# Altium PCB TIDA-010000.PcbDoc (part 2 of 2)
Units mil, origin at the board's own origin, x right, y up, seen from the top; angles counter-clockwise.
Board outline 6158.37 x 2561.06 mil, 2 copper layers (Top Layer, Bottom Layer), stack 62 mil thick; 145 components, 51 nets, 285 pads, 57 vias.
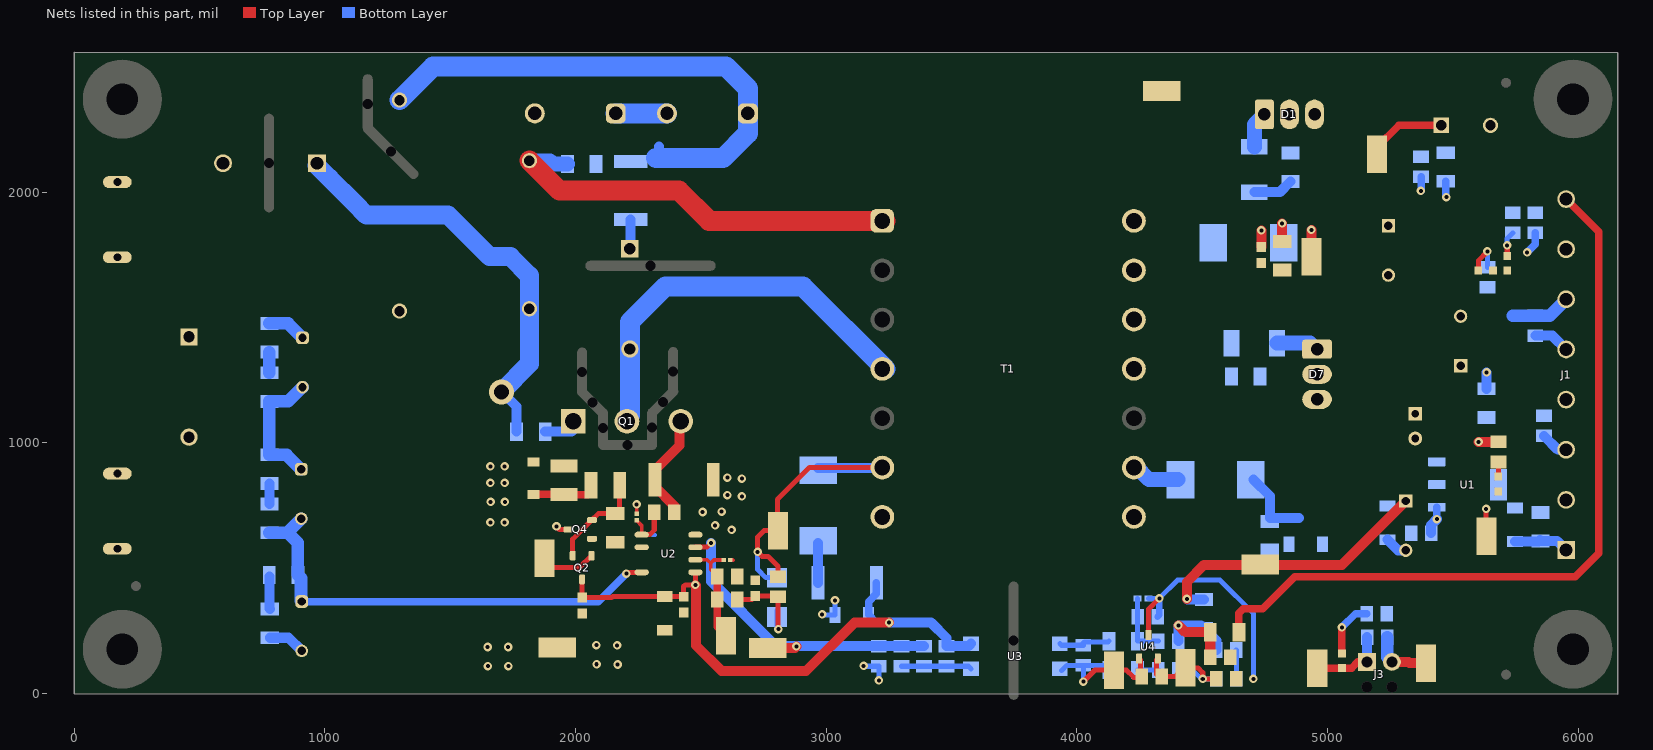
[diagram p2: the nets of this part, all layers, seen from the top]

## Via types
v1: diameter 34, hole 16, Top Layer to Bottom Layer, tented both sides, 56 vias
v2: diameter 100, hole 60, Top Layer to Bottom Layer, tented both sides, 1 vias

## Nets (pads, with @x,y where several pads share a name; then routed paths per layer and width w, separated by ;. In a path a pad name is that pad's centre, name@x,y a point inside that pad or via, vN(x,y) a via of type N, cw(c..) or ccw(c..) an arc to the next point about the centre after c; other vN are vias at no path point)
3V3DC: C26.1 J1.2 R52.2 TP7.1 U1.2 U1.4 | length 110.6
  Top Layer w20: v1(5633.37,737) 5633.37,628.35 TP7.1@5634.72,627
5V_ISO: C18.1 C21.1 C23.1 D13.1 J3.2 R17.2 R43.2 TP4.1 | length 542.6
  Top Layer w40: J3.2@5257.31,126.5 5322.37,126.5 5326.87,122 TP4.1@5393.37,122
  Bottom Layer w40: D13.1@4704.22,854 4770.22,788 4770.22,700.09 4887.13,700.09
  Bottom Layer w50: C23.1@5237.88,225 5237.88,145.93 J3.2@5257.31,126.5
5VDC: C13.1 C16.1 C17.1 C25.1 J1.4 L1.2 R11.2 R35.2 R54.2 TP3.1 U1.3 | length 1218.9
  Top Layer w40: v1(4439.37,378) 4439.37,445.56 4507.81,514 4643.83,514 5057.8,514 C16.1@5312.22,768.43 ; v1(5603.22,1004) R35.2@5682.88,1004
  Bottom Layer w40: v1@4442.28,375.09 R54.2@4507.37,375.09
15VDC: C4.1 C8.1 C12.1 D6.1 J1.6 R5.2 R45.2 TP2.1 | length 485
  Top Layer w40: C8.1@4736.22,1781.5 v1(4736.22,1848) ; R5.2@4819.22,1804.09 v1(4819.22,1875.71) ; TP2.1@4936.22,1743 v1(4936.22,1850)
  Bottom Layer w50: 5739.16,1508 C12.1@5829.16,1508 5887.16,1508 J1.6@5952.16,1573
24VDC: C1.1 C3.1 C5.1 C11.1 D1.2 J1.8 R2.2 R44.2 R53.2 TP1.1 | length 3397.5
  Top Layer w30: R53.2@4646.46,245 4646.37,245.09 4646.37,320.37 4664.47,338.47 4741.69,338.47 4869.22,466 5987.88,466 6081.88,560 6081.88,1843.28 J1.8@5952.16,1973 ; TP1.1@5197.22,2151 5197.22,2178.85 5285.37,2267 C3.1@5453.4,2267
CS: C22.1 R21.2 U2.5 | length 194.6
  Top Layer w15: C22.1@2244.22,690.96 2263.94,671.24 U2.5@2263.94,634
  Top Layer w20: U2.5@2263.94,634 2295.91,634 2314.22,652.31 R21.2@2314.22,723.9
FB: C34.2 R36.1 R39.2 TP13.1 U2.3 | length 1295.5
  Top Layer w20: U2.3@2478.5,584 2524.22,584 v1(2541.22,601)
  Top Layer w40: TP13.1@2767.22,182 2874.72,182 v1(2881.22,188.5)
  Bottom Layer w40: v1(2541.22,601) 2541.22,448 2800.04,189.18 R39.2@3210.09,189.18 C34.2@3390.09,189.18
Gate: D24.2 Q1.1 R19.2 R50.2 | length 115.2
  Bottom Layer w40: R50.2@1879.31,1045 1983.22,1045 Q1.1@1991.22,1053
GND: C3.2 C4.2 C5.2 C8.2 C11.2 C12.2 C13.2 C15.2 C16.2 C17.2 C25.2 C26.2 C27.1 C44.2 D18.2 D20.2 D26.2 D27.2 J1.1 J1.3 J1.5 J1.7 R2.1 R5.1 R11.1 R24.1 R52.1 T1.11 TP11.1 U1.1 U4.3 | length 1959.2
  Top Layer w20: U4.3@4285.7,234.24 4285.7,336.77 v1(4328.93,380)
  Bottom Layer w20: D18.2@4285.93,380 v1(4328.93,380) 4401.8,452.87 4571.35,452.87 4704.04,320.18 v1(4704.04,59.18)
  Bottom Layer w25: C27.1@4322.28,307 4328.93,313.65 v1(4328.93,380)
  Bottom Layer w30: v1(5372.22,2006) 5373.31,2007.09 C5.2@5373.31,2062 ; v1(5436.19,696) U1.1@5436.19,743.45 ; R2.1@5472.31,2043.91 5472.31,1982.91 v1(5474.22,1981) ; v1(5796.88,1760) 5829.16,1792.27 C11.2@5829.16,1838
  Bottom Layer w40: C25.2@5239.22,614.07 5281.72,571.57 C16.2@5312.22,571.57 ; C17.2@5413.31,640 5413.31,673.12 v1(5436.19,696) ; R11.1@5634.88,1216.09 v1(5634.88,1281.66) ; C26.2@5747.88,607.07 5842.04,607.07 R52.1@5847.05,612.08 ; C12.2@5829.16,1428 5897.16,1428 J1.5@5952.16,1373 ; R52.1@5850.22,608.91 5916.24,608.91 J1.1@5952.16,573 ; C13.2@5863.88,1028 5918.88,973 J1.3@5952.16,973
HV_START: C14.2 C20.1 R12.1 R15.2 U2.8 | length 1853.8
  Top Layer w20: v1(2203.22,479) 2208.22,484 U2.8@2263.94,484
  Bottom Layer w30: C20.1@905,370.33 C20.1@907.91,367.43 2091.65,367.43 v1(2203.22,479)
  Bottom Layer w50: R12.1@778.91,642.04 779.5,642.63 851.77,642.63 ; C20.1@905,370.33 905,461.18 R15.2@892.68,473.5 892.68,601.72 851.77,642.63 ; C14.2@905.91,698.1 905.91,696.77 851.77,642.63
ISO_GND: C18.2 C21.2 C23.2 D25.2 J3.1 R17.1 T1.8 TP10.1 | length 307.9
  Top Layer w30: TP10.1@4959.22,102 5056.84,102 D25.2@5057.37,101.47 5095.84,101.47 5120.87,126.5 J3.1@5157.31,126.5
  Top Layer w40: J3.1@5156.98,126.83 J3.1@5157.31,126.5
  Bottom Layer w40: J3.1@5157.31,126.5 5157.31,224.42 C23.2@5157.88,225
NetC1_2: C1.2 R1.2 | length 161.8
  Bottom Layer w40: R1.2@4708.22,2000.45 4809.98,2000.45 C1.2@4852.44,2042.91
NetC2_2: C2.2 D5.1 R4.1 R6.2 | length 2067
  Bottom Layer w40: 2333.08,2183.14 2333.22,2183
  Bottom Layer w80: R4.1@1298.11,2367.87 1431.3,2501.06 2601.16,2501.06 2687.69,2414.53 D5.1@2687.69,2314.78 2687.69,2235.47 2589.22,2137 2321.34,2137
NetC9_2: C9.2 C14.1 R8.1 R10.2 | length 519.3
  Bottom Layer w50: C14.1@905.91,894.95 848,952.86 R10.2@778.91,952.86 R8.1@778.91,1165.6 853.93,1165.6 C9.2@910.91,1222.57
NetC10_1: C10.1 C15.1 D7.2 L1.1
NetC10_2: C10.2 R7.2
NetC27_2: C27.2 D18.1 R9.1 R28.2 | length 254.3
  Bottom Layer w20: D18.1@4242.62,380 4242.28,379.65 C27.2@4242.28,307 4242.18,306.9 R28.2@4242.18,209.18 4325.19,209.18 R9.1@4325.37,209
NetC28_1: C28.1 R29.1 R37.2 TP14.1 U2.2 | length 441.3
  Top Layer w15: U2.2@2478.5,534 2525.05,534 2539.23,519.82 ; R37.2@2566.22,467 2539.23,493.99 2539.23,519.82 ; C28.1@2592.23,532.81 2552.22,532.81 2539.23,519.82
  Top Layer w20: R37.2@2571.22,449 R37.2@2572.22,450
  Top Layer w30: R37.2@2566.22,467 2566.22,377 R29.1@2565.22,376 2565.22,266 TP14.1@2600.22,231
NetC31_2: C31.2 C34.1 R36.2 U3.3 | length 282
  Bottom Layer w20: R36.2@3300.09,109.18 C34.1@3390.09,109.19 C31.2@3480.09,109.18 3567.93,109.18 U3.3@3577.93,99.18
NetC32_1: C32.1 C35.2 R24.2 R31.1 TP9.1 U4.2 | length 490
  Top Layer w20: C35.2@4317.2,77 4317.2,133.85 U4.2@4323.1,139.76 ; C35.2@4338.69,68 4392.22,68 4427.22,103 4483.22,103 4502.4,83.82 v1(4502.4,59.18) R24.2@4556.7,59.18
  Bottom Layer w20: C32.1@4405.09,94.18 4461.04,94.18 v1@4496.04,59.18 ; v1(4502.4,59.18) R31.1@4556.7,59.18
NetC32_2: C32.2 R32.1 | length 82.9
  Bottom Layer w20: R32.1@4242.18,94.18 C32.2@4325.09,94.18
NetC33_1: C33.1 D8.2 R27.1 R29.2 | length 376
  Top Layer w20: R29.2@2645.22,376 2703.41,376 C33.1@2716.91,389.5 2804.72,389.5 R27.1@2808.22,386 2808.22,258.41 v1(2809.22,257.41)
  Bottom Layer w20: D8.2@2804.22,332.26 2804.22,262.41 v1(2809.22,257.41)
NetC35_1: C35.1 R13.1 R32.2 TP5.1 U3.2 U4.1 | length 615.1
  Top Layer w20: v1(4026.37,48) 4072.37,94 TP5.1@4149.22,94 4197.8,94 4226.8,65 C35.1@4254.2,65 ; U4.1@4248.3,139.76 4254.2,133.85 C35.1@4254.2,65 ; C35.1@4258.69,68 4255.69,65 C35.1@4254.2,65
  Bottom Layer w20: U3.2@3939.34,92.1 3960.24,113 R13.1@4025.9,113 ; v1(4026.37,48) 4025.9,48.47 R13.1@4025.9,113 ; R32.2@4125.92,92.1 R32.2@4128,94.18 4109.19,113 R13.1@4025.9,113
NetC44_1: C44.1 R9.2 R26.2 R53.1 R54.1 | length 517.4
  Top Layer w40: v1(4405.37,272.66) 4433.03,245 R53.1@4532.28,245 ; C44.1@4526.74,147.09 C44.1@4528.83,145 ; C44.1@4532.37,145 R53.1@4532.37,242.91
  Bottom Layer w40: R9.2@4405.37,209 v1(4405.37,272.66) 4495.62,272.66 R54.1@4507.37,260.91 4556.7,211.59 R26.2@4556.7,174.18 R26.2@4556.37,174.51
NetD1_1: D1.1 D1.3 R1.1 T1.14 | length 146
  Bottom Layer w60: R1.1@4708.22,2181.55 4708.22,2270.73 D1.1@4748.37,2310.88
NetD2_1: D2.1 D5.2 | length 204.2
  Bottom Layer w80: D2.1@2160.64,2314.78 D5.2@2364.86,2314.78
NetD3_2: D3.2 F2.1 F2.2
NetD4_1: D4.1 R6.1 | length 97.4
  Bottom Layer w40: D4.1@2216.79,1794.9 2220.22,1798.33 R6.1@2220.22,1890.86
NetD4_2: D4.2 Q1.2 T1.4 | length 1602.3
  Bottom Layer w80: Q1.2@2205.37,1098.6 2216.79,1110.02 D4.2@2216.79,1375 2216.79,1482.57 2358.22,1624 2907.15,1624 T1.4@3235.7,1295.45
NetD6_2: D6.2 T1.13
NetD7_1: D7.1 D7.3 R7.1 T1.12 | length 165.4
  Bottom Layer w60: R7.1@4798.77,1398 4930.22,1398 D7.1@4954.22,1374
NetD12_1: D12.1 R14.2 | length 159.1
  Bottom Layer w40: R14.2@2968.08,442 2968.08,600.86 D12.1@2968.22,601
NetD13_2: D13.2 T1.9 | length 184.4
  Bottom Layer w60: T1.9@4239.64,901.75 4287.39,854 D13.2@4404.22,854
NetD20_1: D20.1 R35.1 | length 59.2
  Top Layer w20: D20.1@5681.14,865.53 5682.88,867.27 R35.1@5682.88,924
NetD24_1: D24.1 R19.1 R48.2 | length 259
  Top Layer w30: D24.1@1833.22,794.53 1953.52,794.53 R19.1@1954.13,793.91 2049.76,793.91 2062.09,806.24 R48.2@2062.09,831
NetD25_1: D25.1 R43.1 | length 226.1
  Top Layer w30: D25.1@5057.37,160.53 v1(5057.37,264.49)
  Bottom Layer w30: v1(5057.37,264.49) 5111.88,319 R43.1@5156.88,319
NetD26_1: D26.1 R44.1 | length 101
  Top Layer w20: v1(5716.73,1788) 5717.22,1787.51 D26.1@5717.22,1746.53
  Bottom Layer w20: v1(5716.73,1788) 5716.73,1815.57 R44.1@5739.16,1838
NetD27_1: D27.1 R45.1 | length 154.3
  Top Layer w20: D27.1@5601.69,1688 5601.69,1727.47 v1(5638.22,1764)
  Bottom Layer w20: v1(5638.22,1764) 5638.72,1763.5 R45.1@5638.72,1701
NetF1_1: F1.1 F1.2 J2.2
NetQ1_3: Q1.3 R21.1 R23.2 | length 414.6
  Top Layer w40: R21.1@2394.22,723.9 2394.22,749 2317.08,826.14 R23.2@2317.08,854 2317.08,891.86 2414.91,989.69 Q1.3@2414.91,1066
NetQ2_1: Q2.1 Q4.1 R18.2 TP12.1 U2.6 | length 222.8
  Top Layer w20: TP12.1@1875.72,540 1912.72,503 2016.38,503 Q2.1@2063.62,550.24
NetQ2_2: Q2.2 Q4.2 R18.1 R48.1 | length 397.8
  Top Layer w20: Q2.2@1988.82,550.24 1988.82,616.03 2065.19,692.4 Q4.2@2065.61,692.4 2091.29,718.09 R18.1@2158.22,718.09 2176.26,736.13 R48.1@2176.26,831
NetR3_1: R3.1 R8.2 | length 82.8
  Bottom Layer w50: R8.2@778.91,1279.77 R3.1@778.91,1362.6
NetR10_1: R10.1 R12.2 | length 82.5
  Bottom Layer w40: R12.2@778.91,756.21 R10.1@778.91,838.69
NetR13_2: R13.2 R28.1 U3.1 | length 205.3
  Bottom Layer w20: U3.1@3932.26,199.18 3938.44,193 R13.2@4025.9,193 ; R13.2@4023,199.18 4030.09,206.27 4125.09,206.27 R28.1@4128,209.18
NetR15_1: R15.1 R16.2 | length 131.4
  Bottom Layer w40: R15.1@778.91,467.81 778.91,338.77 R16.2@780.59,337.09
NetR26_1: R26.1 R31.2 | length 118.7
  Bottom Layer w20: R31.2@4634.7,59.18 4636.7,61.18 R26.1@4636.7,172.18 ; R26.1@4634.7,174.18 R26.1@4636.7,172.18 ; R26.1@4636.7,174.18 R26.1@4636.7,172.18
PGND: C7.2 C19.2 C20.2 C22.2 C24.2 C28.2 C29.2 C30.2 C33.2 J2.1 Q4.3 R16.1 R23.1 R37.1 R39.1 R50.1 T1.7 TP15.1 U2.4 | length 2203.7
  Top Layer w15: C22.2@2244.22,717.89 v1(2244.22,755) ; C28.2@2627.22,534 2629.22,532
  Top Layer w20: v1(1924.22,667) 1936.22,655 Q4.3@1971.12,655
  Bottom Layer w15: 2306.22,634 2307.22,633 2318.22,633
  Bottom Layer w20: v1(2984.22,316) 2986.22,314 C19.2@3035.29,314 v1(3035.29,372) ; v1(3149.22,111) 3151.04,109.19 R39.1@3210.09,109.19 3210.09,53.13 v1(3210.22,53)
  Bottom Layer w40: R16.1@780.59,222.91 855.57,222.91 C20.2@907.91,170.57 ; v2@1705.22,1205 1765.13,1145.09 R50.1@1765.13,1045
  Bottom Layer w75: J2.1@968.77,2106.43 1018.1,2057.1 1116.76,1958.44 1166.09,1909.11 1491.79,1909.11 1657.59,1743.3 1740.66,1743.3 1816.22,1667.74 C7.2@1816.22,1535.72 1816.22,1316 v2@1705.22,1205
  other v1: 1650.64,110 1732.64,110 2167.64,116.16 2084.64,117.19 1649.22,186 1731.22,186 2166.22,192.16 2083.22,193.19 2623.22,653 2557.22,671 1660.06,683 1717.06,683 2507.22,724.58 2583.22,726 1661.64,765 1718.64,765 2663.37,787 2606.22,791.65 1660.22,841 1717.22,841 2663.37,857.35 2606.22,862 1660.22,907 1717.22,907
  other v2: 1705.22,1204
VDC: C2.1 C7.1 C9.1 D2.2 D3.1 R3.2 R4.2 T1.1 | length 1832.2
  Top Layer w80: C7.1@1816.22,2126.28 1935.5,2007 2412.22,2007 2533.22,1886 T1.1@3235.7,1886
  Bottom Layer w50: R3.2@778.91,1476.77 853.56,1476.77 C9.1@910.91,1419.43
  Bottom Layer w60: C7.1@1816.22,2126.28 1816.73,2125.76 1899.08,2125.76 1911.84,2113 C2.1@1968.13,2113
VDD: C19.1 C24.1 C29.1 C30.1 C31.1 Q2.3 R14.1 U2.1 U3.4 | length 2380.9
  Top Layer w20: Q2.3@2026.22,455.76 2026.22,383.33 C30.1@2026.65,382.9 2144.62,382.9 2149.22,387.5 2286.22,387.5 2286.79,386.93 C29.1@2356.22,386.93 2430.79,386.93 C24.1@2431.22,386.5 2431.22,427 2438.22,434 2478.28,434 v1(2478.5,433.78) U2.1@2478.5,484
  Top Layer w40: v1(2478.5,433.78) 2481.22,431.06 2481.22,192 2583.22,90 2920.05,90 3113.05,283 v1(3251.28,283)
  Bottom Layer w30: R14.1@3200.36,442 3200.36,397.8 3169.15,366.58 C19.1@3169.15,314 3200.15,283 v1(3251.28,283)
  Bottom Layer w40: v1(3251.28,283) 3419.22,283 3480.09,222.13 C31.1@3480.09,189.18 3567.93,189.18 U3.4@3577.93,199.18
VFB: D8.1 D12.2 R27.2 T1.6 TP8.1 | length 1293.8
  Top Layer w20: TP8.1@2800.22,694 2806.22,700 2806.22,775.26 2932.71,901.75 T1.6@3235.7,901.75 ; TP8.1@2807.22,650 2752.22,650 2726.72,624.5 2726.22,625 v1(2726.22,565.75) 2743.98,548 2768.22,548 2808.22,508 R27.2@2808.22,466
  Bottom Layer w20: v1(2726.22,565.75) 2726.22,495.78 2759.26,462.74 D8.1@2804,462.74
  Bottom Layer w40: D12.2@2968.22,901 3234.95,901 T1.6@3235.7,901.75
pads on no net: FID1.1 FID2.1 FID3.1 FID4.1 FID5.1 FID6.1 H1.1 H2.1 H3.1 H4.1 H5.0 H6.0 H7.0 H8.0 J3.MH1 J3.MH2 T1.2 T1.3 T1.5 T1.10

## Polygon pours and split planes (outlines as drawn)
GND on Top Layer "GND_L01_P218" (solid, remove dead copper, pour order 218): 4459.18,1186.19 4459.18,690.96 4159.25,391.03 4159.25,95.63 4234.88,20 4710.62,20 4715.37,24.67 4715.37,232 4901.95,418.58 6024.8,418.58 6135.22,529 6135.22,2092 6082.22,2144 5925.37,2144 5753.22,2316.15 5532.37,2537 4283.22,2537 4180.22,2434 4180.22,1838 4214.22,1804 4415,1804 4415,1619.24 4407.72,1615 4193.22,1615 4180.22,1602 4180.22,1239.72 4191.94,1228 4417.37,1228 4447.18,1198.19
PGND on Top Layer "PGND_L01_P226" (solid, remove dead copper, pour order 226): 3306.22,553 3306.22,334.5 3335.87,304.85 3335.87,304 3555.22,304 3617.29,241.92 3617.3,66.93 3574.41,24.04 3277.59,24.04 3276.37,22.82 3276.37,22 1227.65,22 1120.22,22 1118.18,24.04 906.33,28.04 882.37,52 882.37,221.7 910.03,249.35 1480.58,249.35 1532.22,301 1533.71,768.49 1639.22,874 1639.22,1033 1639.22,1060.29 1639.22,1246.82 1660.4,1268 1757.22,1268 1768.22,1257 1768.22,407 1836.17,339.06 2320.28,339.05 2386.22,405 2386.22,645 2405.22,664 2442.22,664 2467.22,689 2467.22,752 2506.22,791 2506.22,912.08 2538.14,944 2601.37,944 2687.69,857.68 2687.69,640.53 2766.22,562 2766.22,451.31 2748.69,433.78 2618.5,433.78 2609.22,443.06 2609.22,603 2583.22,629 2525.22,629 2512.22,616 2455.22,616 2433.22,594 2433.22,465 2450.22,448 2450.22,217 2530.22,137 3137.22,137 3175.22,175 3175.22,759 3196.22,780 3289.84,780 3306.22,763.62
NetD1_1 on Top Layer "NETD1_1_L01_P210" (solid, remove dead copper, pour order 210): 4563.22,2353 4615.22,2405 5003.38,2405 5031.88,2376.5 5031.88,2259.24 4974.65,2202 4734.22,2202 4509.22,1977 4359.22,1827 4199.8,1827 4177.37,1849.43 4177.37,1967.15
NetD7_1 on Top Layer "NETD7_1_L01_P198" (solid, remove dead copper, pour order 198): 4190.37,1561 4997,1561 5056.84,1501.16 5056.84,1113.84 5037,1094 4870.96,1094 4835.22,1129.74 4835.22,1325 4740.8,1419.43 4191.67,1419.42 4179.37,1431.72 4179.37,1550
NetF1_1 on Top Layer "NETF1_1_L01_P000" (solid, remove dead copper, pour order 0): 569.37,2152 622.68,2152 630.37,2144.31 630.37,2022.95 539.4,1931.97 314.43,1707 126,1707 102,1731 102,2047 126,2071 415.43,2071 488.37,2071
NetD3_2 on Top Layer "NETD3_2_L01_P002" (solid, remove dead copper, pour order 2): 187.29,1060.29 477.53,1060.29 497.37,1040.45 497.37,581.75 464.57,548.96 124.52,548.96 108,565.48 108,981
VDC on Top Layer "VDC_L01_P004" (solid, remove dead copper, pour order 4): 1160,1610 458.37,1610 423.37,1575 423.37,1418.32 449.69,1392 1257.37,1392 1455.22,1589.85 1455.22,1685 1807.22,2037 2004.22,2037 2004.22,2046 1883.22,2167 1883.22,2328 1861.22,2350 1817.22,2350 1797.22,2330 1797.22,2247.22
NetQ2_1 on Top Layer "NETQ2_1_L01_P234" (solid, remove dead copper, pour order 234): 2195.06,635.32 2226.46,603.91 2295.5,603.91 2302.41,597 2302.41,574.19 2294.73,566.51 2136.73,566.51 2097.83,527.61 2040.43,527.61 2026.22,541.81 2026.22,623.16 2038.38,635.32
Gate on Top Layer "GATE_L01_P236" (solid, remove dead copper, pour order 236): 1849.7,1107.89 1851.26,1107.89 1893.37,1150 1894.37,1149 2041.22,1149 2041.22,911 2004.22,874 1821.17,874 1797.22,897.95 1797.22,1055.41
NetC10_2 on Bottom Layer "NETC10_2_L02_P238" (solid, remove dead copper, pour order 238): 4657.37,1471 4665.37,1463 4665.37,1348.76 4643.37,1326.76 4643.37,1227 4627.37,1211 4565.37,1211 4543.46,1232.91 4543.46,1458.09 4556.37,1471
NetC2_2 on Bottom Layer "NETC2_2_L02_P232" (solid, remove dead copper, pour order 232): 2055.72,2201 2348.72,2201 2366.72,2183 2366.72,2112 2322.72,2068 2066.72,2068 2055.72,2079
PGND on Bottom Layer "PGND_L02_P230" (solid, remove dead copper, pour order 230): 977.72,255 908.37,255 882.37,229 882.37,56 906.37,32 977.22,32 3230.37,32 3258.37,60 3258.37,220 3155.37,323 3155.37,367 3119.37,406 2848.22,406 2809.22,445 2805.92,1046.52 2760.07,1075 2570.56,1075 2536.22,1013.44 2536.22,925.86 2475.36,865 1867.83,865 1768.83,964 1653.8,964 1641.22,951.42 1641.22,641 1657.22,625 2191.22,625 2292.22,524 2292.22,320.41 2226.81,255
3V3DC on Bottom Layer "3V3DC_L02_P216" (solid, remove dead copper, pour order 216): 5394.22,858 5567.82,858 5613.82,904 5934.22,904 6009.22,829 6009.22,714 5989.22,694 5634.37,694 5522.37,806 5396.22,806 5390.22,812 5390.22,854
5VDC on Bottom Layer "5VDC_L02_P214" (solid, remove dead copper, pour order 214): 5182.3,921.07 5182.3,700.54 5196.84,686 5269.31,686 5287.37,666.94 5287.37,613 5300.37,600 5354.37,600 5362.37,608 5362.37,743.85 5360.22,746 5360.22,873 5377.22,890 5547.22,890 5736.22,1079 5957.22,1079 6012.22,1134 6012.22,1199 5990.22,1221 5769.22,1221 5689.22,1141 5563.22,1141 5479.22,1057 5318.22,1057
24VDC on Bottom Layer "24VDC_L02_P212" (solid, remove dead copper, pour order 212): 5631.37,2439 6005.22,2065.15 6005.22,1935 5961.22,1891 5700.22,1891 5646.22,1945 5646.22,2016 5551.22,2111 4821.22,2111 4808,2124.22 4808,2388 4859,2439
15VDC on Bottom Layer "15VDC_L02_P208" (solid, remove dead copper, pour order 208): 4749.22,1913 5144.22,1913 5318.22,1913 5566.22,1665 5992.22,1665 6013.22,1644 6013.22,1510.58 5971.64,1469 4891.37,1469 4702.22,1658.15 4702.22,1866
NetD6_2 on Bottom Layer "NETD6_2_L02_P206" (solid, remove dead copper, pour order 206): 4199,1749 4344.22,1749 4479.22,1884 4593.22,1884 4601.22,1876 4601.22,1692 4537.22,1628 4208,1628 4180.98,1655.02 4180.98,1730.98
5V_ISO on Bottom Layer "5V_ISO_L02_P204" (solid, remove dead copper, pour order 204): 5057.37,606.46 5057.37,522.76 5121.13,459 5204.1,459.73 5305.22,358.61 5305.22,103 5282.22,80 5238.22,80 5213.22,105 5213.22,364 5184.8,392.43 4994.37,392 4959.22,427.15 4959.22,585 4883.22,661 4699.12,661 4640.22,719.9 4640.22,936 4649.22,945 4801.22,945 5057.37,688.85
ISO_GND on Bottom Layer "ISO_GND_L02_P202" (solid, remove dead copper, pour order 202): 5094.5,265 5082.37,252.87 5082.37,209.53 5065.38,192.54 5028.05,192.54 5016.37,204.22 5016.37,273.85 4937.22,353 4937.22,490.54 4937.22,556 4868.22,625 4691.22,625 4553.22,763 4188.22,763 4173.22,748 4173.22,625 4195.22,603 4614.92,603 4922.37,290.47 4922.37,135.47 4979.84,78 5118.22,78 5142.93,78 5186.22,78 5199.22,91 5199.22,248 5182.22,265
NetC10_1 on Bottom Layer "NETC10_1_L02_P200" (solid, remove dead copper, pour order 200): 5049.43,1315.2 5123.22,1389 5531.22,1389 5574.22,1346 5574.22,1227 5433.22,1086 5149.8,1086 5002.89,1232.91 4705,1232.91 4705,1304 4716.2,1315.2

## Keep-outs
Keep-Out Layer:
  text ".Layer_Name" at -324.44,-1042.35 h60

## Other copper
Top Layer:
  pour cut-out: 2386.37,593 2433.06,593 2433.37,544 2386.37,544
  text ".Layer_Name" at -324.44,-1042.35 h60
Bottom Layer:
  text ".Layer_Name" at -324.44,-1042.35 h60

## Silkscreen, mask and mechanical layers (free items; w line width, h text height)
Top Overlay:
  circle w10: c5150.83,289 r13
  lines w6: 2208.57,2443 2208.57,2509 ; 2735.87,2439.5 2735.87,2505.5 ; 2175.57,2443 2208.57,2476 2175.57,2509 2175.57,2443 ; 2702.87,2439.5 2702.87,2505.5 2735.87,2472.5 2702.87,2439.5
  lines w10: 4210.37,225.07 4210.37,195.56 4222.37,183.56 4222.37,122
  text "+" at 268,2099 h78.74
  text "1000V, 50W" at 488.37,1822 h60
  text "1000V, 2.5A FUSE ONLY" at 251.37,956.87 h35 r90
  text ".Layer_Name" at -324.44,-1042.35 h60
Bottom Overlay:
  lines w6: 3088.22,77 3112.22,53 3499.22,53
  text ".Layer_Name" at -324.44,-1042.35 h60
Top Paste:
  text ".Layer_Name" at -324.44,-1042.35 h60
Bottom Paste:
  text ".Layer_Name" at -324.44,-1042.35 h60
Top Solder:
  text ".Layer_Name" at -324.44,-1042.35 h60
  text ".Layer_Name" at -324.44,-1042.35 h60
Bottom Solder:
  text ".Layer_Name" at -324.44,-1042.35 h60
Drill Guide:
  text ".Layer_Name" at -324.44,-1042.35 h60
M1 Board Outline:
  lines w10: 0,2557.05 6157.71,2557.06 6157.71,-2 ; 0,2559.06 0,0 6158.37,0
M2 Board Dimensions:
  rectangle: -836.49,-583.85 -461.49,-458.85
  rectangle: -961.49,-458.85 -836.49,-333.85
  lines w7: -961.49,-458.85 38.51,-458.85 ; -836.49,-583.85 -836.49,-333.85 ; -711.49,-583.85 -711.49,-333.85 ; -461.49,-583.85 -461.49,-333.85 ; -211.49,-583.85 -211.49,-333.85 ; -961.49,-583.85 -961.49,-333.85 38.51,-333.85 38.51,-583.85 -961.49,-583.85
M3 3D STEP Top:
  text ".Layer_Name" at -324.44,-1042.35 h60
M4 3D STEP Bottom:
  text ".Layer_Name" at -324.44,-1042.35 h60
M5 Assembly Top:
  circle w10: c2311,481 r6.24
  circle w10: c973,2029 r20.62
  circle w10: c5821,418 r18.44
  lines w6: 1900.79,2215.37 cw(c1837.8,2314.78) 1900.8,2414.19 ; 1901.48,2414.19 2220.64,2414.19 2220.64,2215.37 ; 1902.37,2215.37 2222.22,2215.37 ; 2747.01,2414.19 2427.85,2414.19 ccw(c2364.86,2314.78) 2427.84,2215.37 2747.7,2215.37 ; 2747.69,2215.37 2747.69,2414.19
  lines w10: -1193.44,-1114.02 5406.56,-1114.02 ; -1193.44,-910.69 5408.56,-910.69 ; -1193.44,-707.35 -1193.44,-1317.35 2811.56,-1317.35 5408.56,-1317.35 5408.56,-707.36 -1192.94,-707.36 -1192.94,-1317.35 382.56,-1317.35 ; 1271.56,-1317.35 1271.56,-707.36 ; 2538.56,-910.69 2538.56,-707.36 ; 3378.56,-910.69 3378.56,-707.36 ; 4000.56,-1323.85 4000.56,-1121.02
  text "COMPONENTS MARKED 'DNP' SHOULD NOT BE POPULATED." at 252.06,-502.35 h60
  text "ASSEMBLY VARIANT:" at 251.56,-617.85 h60
  text ".VariantName" at 1287.56,-617.85 h60
  text "PCB VIEWED FROM TOP SIDE" at -1129.94,-839.52 h60
  text "BOARD #:" at 1346.56,-839.52 h60
  text ".PRJ_Number" at 1892.06,-839.52 h60
  text "REV:" at 2736.56,-839.52 h60
  text ".PCB_Rev" at 3028.06,-839.52 h60
  text "SVN REV:" at 3574.56,-839.52 h60
  text ".VersionControl_RevNumber" at 4080.56,-839.52 h60
  text "TID #:" at 1346.56,-1042.86 h60
  text ".TID" at 1892.06,-1042.86 h60
  text "'.Layer_Name'" at -286.49,-1043.85 h60
  text ".plot_File_Name" at -492.34,-1235.85 h40
  text "PLOT NAME =" at -1169.34,-1245.85 h60
  text "GENERATED    :" at 1348.56,-1248.19 h60
  text ".Print_Date" at 2218.06,-1248.19 h60
  text ".Print_Time" at 2947.06,-1248.19 h60
  text "TEXAS INSTRUMENTS" at 4211.56,-1248.19 h60
M6 Assembly Bottom:
  circle w10: c3860,210 r10.3
  lines w10: -1193.94,-911.19 5408.06,-911.19 ; -1191.94,-1114.52 5408.06,-1114.52 ; 214.06,-1324.35 214.06,-1121.52 ; 836.06,-911.19 836.06,-707.86 ; 1676.06,-911.19 1676.06,-707.86 ; 2943.06,-1317.85 2943.06,-707.86 ; 3832.06,-1317.85 5407.56,-1317.85 5407.56,-707.85 -1193.94,-707.86 -1193.94,-1317.85 1403.06,-1317.85 5408.06,-1317.85 5408.06,-707.85
  text "COMPONENTS MARKED 'DNP' SHOULD NOT BE POPULATED." at 5200.56,-501.85 h60
  text ".VariantName" at 4156.56,-617.85 h60
  text "ASSEMBLY VARIANT:" at 5195.56,-617.85 h60
  text ".VersionControl_RevNumber" at 134.06,-840.02 h60
  text "SVN REV:" at 640.06,-840.02 h60
  text ".PCB_Rev" at 1186.56,-840.02 h60
  text "REV:" at 1478.06,-840.02 h60
  text ".PRJ_Number" at 2322.56,-840.02 h60
  text "BOARD #:" at 2868.06,-840.02 h60
  text "PCB VIEWED FROM BOTTOM SIDE" at 5344.56,-840.02 h60
  text ".TID" at 2322.56,-1043.36 h60
  text "TID #:" at 2868.06,-1043.36 h60
  text "'.Layer_Name'" at 4737.51,-1043.85 h60
  text "TEXAS INSTRUMENTS" at 3.06,-1248.69 h60
  text ".Print_Time" at 1267.56,-1248.69 h60
  text ".Print_Date" at 1996.56,-1248.69 h60
  text "GENERATED    :" at 2866.06,-1248.69 h60
  text ".plot_File_Name" at 4539.06,-1248.69 h60
  text "PLOT NAME =" at 5344.56,-1248.69 h60
M9 Title Sheet:
  drawing of 57 lines, arcs and shapes, not listed
  text "1" at -161.6,7852.65 h70
  text "2" at 2334.06,7852.65 h70
  text "3" at 4823.41,7852.65 h70
  text "4" at 7330.08,7852.65 h70
  text "5" at 9829.06,7852.65 h70
  text "6" at 12334.06,7852.65 h70
  text "A" at -1317.94,6709.65 h70
  text "A" at 13482.06,6709.65 h70
  text "B" at -1317.94,4329.65 h70
  text "B" at 13482.06,4329.65 h70
  text "C" at -1317.94,1954.65 h70
  text "C" at 13482.06,1954.65 h70
  text "PROJECT TITLE:" at 10442.06,93.65 h45
  text ".PRJ_Title" at 10492.06,-39.68 h60
  text "DESIGNED FOR:" at 10442.06,-207.35 h45
  text ".PRJ_Customer" at 10492.06,-347.35 h70
  text "D" at -1317.94,-415.35 h70
  text "D" at 13482.06,-415.35 h70
  text "FILE NAME:" at 10442.06,-507.35 h45
  text ".PCB_File_Name_No_Path" at 10492.06,-627.35 h70
  text "Texas Instruments (TI) and/or its licensors do not warrant the accuracy or completeness of this specification" at 5472.56,-789.19 h45
  text "ENGINEER:" at 10442.06,-797.35 h45
  text "LAYOUT BY:" at 11947.06,-797.35 h45
  text "or any information contained therein. TI and/or its licensors do not warrant that this design will meet" at 5427.58,-901.86 h45
  text ".PRJ_Engineer" at 10492.06,-952.35 h70
  text ".PCB_Layout" at 11997.56,-952.35 h70
  text "the specifications, will be suitable for your application or fit for any particular purpose, or will operate in" at 5427.58,-1014.52 h45
  text "ALTIUM DESIGNER VERSION:" at 11947.06,-1107.35 h45
  text "an implementation. TI and/or its licensors do not warrant that the design is production worthy. You should" at 5427.58,-1127.19 h45
  text "completely validate and test your design implementation to confirm the system functionality for your application." at 5472.56,-1239.85 h45
  text ".print_Scale" at 10492.06,-1240.68 h70
  text ".Application_BuildNumber" at 11997.56,-1240.68 h70
  text "1" at -161.6,-1447.35 h70
  text "2" at 2334.06,-1447.35 h70
  text "3" at 4823.41,-1447.35 h70
  text "4" at 7330.08,-1447.35 h70
  text "5" at 9829.06,-1447.35 h70
  text "6" at 12334.06,-1447.35 h70
M10 Fab Notes:
  drawing of 189 lines, arcs and shapes, not listed
  text "DESIGN INFORMATION" at 11480.58,6172.32 h60
  text "MIN. TRACK WIDTH:" at 10836.02,6040.19 h60
  text "15" at 11932.27,6040.2 h60
  text "MIL" at 12087.02,6040.19 h60
  text "MIN. CLEARANCE:" at 10836.02,5916.07 h60
  text "0.2" at 11872.27,5916.07 h60
  text "mm" at 12087.02,5916.07 h60
  text "MIN. VIA PAD SIZE:" at 10836.02,5791.94 h60
  text "34" at 11902.28,5791.94 h60
  text "MIL" at 12087.02,5791.94 h60
  text "0.05mm (2MIL)" at 11531.02,5662.04 h60
  text "MINIMUM ANNULAR RING" at 10506.79,5653.82 h60
  text "EXTERNAL" at 12239.02,5653.82 h60
  text "PER" at 10706.79,5543.69 h60
  text "IPC-D-275 CLASS 2 LEVEL C" at 10926.79,5543.69 h60
  text "MIL, HOLES" at 12415.02,5443.21 h60
  text "+/-" at 12022.56,5434.63 h60
  text "+/-" at 12876.56,5434.63 h60
  text "REGISTRATION TOLERANCES:" at 10506.79,5433.56 h60
  text "METAL" at 11706.56,5433.56 h60
  text "5" at 12282.77,5433.57 h60
  text "3" at 13115.77,5433.57 h60
  text "MIL" at 13232.02,5433.56 h60
  text "HOLE SIZE TOLERANCE (UNLESS OTHERWISE SPECIFIED):" at 10506.79,5335.25 h60
  text "+/-" at 12876.56,5332.38 h60
  text "3" at 13115.77,5331.31 h60
  text "MIL" at 13232.02,5331.31 h60
  text "MATERIAL:" at 10432.02,5193.66 h60
  text "FR-4 High Tg" at 11418.47,5065.14 h60
  text "X" at 11274.03,5057.15 h60
  text "FR-408" at 10853.03,5052.63 h60
  text "OTHER" at 12341.02,5052.63 h60
  text "63 MIL (1.6mm) +/-10%" at 11173.13,4909.6 h60
  text "X" at 11053.03,4907.15 h60
  text "THICKNESS:" at 10506.79,4901.38 h60
  text "OTHER" at 12458.02,4901.38 h60
  text "TOLERANCE:" at 10506.79,4763.07 h60
  text "X" at 11355.03,4763.07 h60
  text "ANSI IPC-6012 TYPE 3 CLASS 2" at 11533.04,4763.07 h60
  text "OTHER +/-" at 11533.02,4618.88 h60
  text "BOW & TWIST:" at 10506.79,4473.69 h60
  text "X" at 11355.03,4473.69 h60
  text "ANSI IPC-6012 TYPE 3 CLASS 2" at 11533.04,4473.69 h60
  text "OTHER +/-" at 11533.02,4326.99 h60
  text "DRILLING:" at 10432.02,4196.37 h60
  text "NC_DRILL FILES" at 12193.02,4091.19 h60
  text "REFERENCE:" at 10506.79,4087.25 h60
  text "X" at 11164.03,4087.15 h60
  text "AS SHOWN" at 11342.02,4087.25 h60
  text "X" at 12065.03,4087.25 h60
  text "OTHER" at 12491.02,3945 h60
  text "PTH COPPER THICKNESS:" at 10506.47,3941.47 h60
  text "X" at 11645.71,3941.47 h60
  text "20-30 um" at 11773.7,3941.47 h60
  text "BOARD FINISH:" at 10432.02,3793.87 h60
  text "SILKSCREEN:" at 10587.25,3683.74 h60
  text "X" at 11545.03,3683.74 h60
  text "TOP" at 11662.02,3683.74 h60
  text "X" at 12055.03,3683.74 h60
  text "BOTTOM" at 12173.02,3683.74 h60
  text "SILKSCREEN COLOR:" at 10587.25,3528.56 h60
  text "X" at 11544.03,3528.56 h60
  text "WHITE" at 11662.02,3528.56 h60
  text "OTHER" at 12173.02,3528.56 h60
  text "X" at 11675.03,3385.11 h60
  text "GREEN" at 11793.02,3385.11 h60
  text "OTHER" at 12411.02,3385.11 h60
  text "SOLDER RESIST COLOR:" at 10587.25,3378.24 h60
  text "X" at 11675.03,3230.86 h60
  text "MATTE" at 11793.02,3230.86 h60
  text "SEMI-GLOSS" at 12410.56,3230.22 h60
  text "IMMERSION GOLD (ENIG)" at 11493.02,3058.08 h60
  text "ENEPIG" at 12830.56,3050.86 h60
  text "SURFACE FINISH:" at 10432.02,3049.86 h60
  text "X" at 11314,3050 h60
  text "IMM. TIN/SILVER OR EQUIV" at 10761.56,2912.55 h60
  text "OTHER" at 12193.02,2908.61 h60
  text "ARRAY/PANEL:" at 10432.02,2753.23 h60
  text "CUT AND TRIM PER M1 BOARD OUTLINE" at 11493.02,2745.01 h60
  text "N.C. ROUTE" at 11493.02,2609.04 h60
  text "X" at 12181.03,2609.04 h60
  text "V. SCORE" at 12359.02,2609.04 h60
  text "CERTIFICATION:" at 10432.02,2479.92 h60
  text "MATERIALS AND WORKMANSHIP FOR ALL PCBS" at 11157.02,2479.92 h60
  text "TO MEET OR EXCEED THE REQUIREMENTS OF:" at 11157.02,2385.85 h60
  text "X" at 10794.53,2257.23 h60
  text "ANSI IPC-A-600F CLASS ->" at 10922.53,2257.23 h60
  text "X" at 12570.53,2257.23 h60
  text "2" at 12680.53,2257.23 h60
  text "1" at 12365.53,2255.73 h60
  text "3" at 13034.53,2255.73 h60
  text "X" at 11606.53,2109.54 h60
  text "RoHS" at 11734.53,2109.54 h60
  text "OTHER" at 12378.93,2109.54 h60
  text "PER ORDER" at 12775.99,2109.54 h60
  text "ALL BOARDS MUST MEET OR EXCEED UL94-V0 REQUIREMENTS." at 10459.56,1955.71 h60
  text "PCB MUST BEAR THE UL94V-0 UL REGISTERED MATERIAL ID NUMBER" at 10459.56,1839.65 h60
  text "ADDITIONAL REQUIREMENTS:" at 10432.02,1670.22 h60
  text "MICROSECTION:" at 10506.79,1563.1 h60
  text "YES" at 11412.53,1563.1 h60
  text "REQUIRED" at 12274.02,1418.77 h60
  text "BARE BOARD ELEC. TEST:" at 10506.79,1415.91 h60
  text "NONE" at 11812.53,1415.91 h60
  text "X" at 12156.03,1415.91 h60
  text "PER ORDER" at 12866.02,1415.91 h60
  text "XX MIL VIAS REQUIRE NON-CONDUCTIVE FILL AND PLANARIZE" at 10674.94,1210.96 h59
  text "XX MIL VIAS REQUIRE CONDUCTIVE FILL AND PLANARIZE" at 10682.94,1106.99 h60
  text "OUTER XX MIL TRACES REQUIRE 50 OHM SINGLE-ENDED IMPEDANCE" at 10681.96,943.6 h55
  text "LAYER 2 & 3 (INNER LAYERS) XX MIL WIDE, XX MIL SPACE / TRACES REQUIRE 100 OHM DIFFERENTIAL IMPEDANCE" at 10673.96,707.89 h60
M11 Gerber Information:
  lines w10: -1193.44,-1114.02 5406.56,-1114.02 ; -1193.44,-910.69 5408.56,-910.69 ; -1193.44,-707.35 -1193.44,-1317.35 2811.56,-1317.35 5408.56,-1317.35 5408.56,-707.36 -1192.94,-707.36 -1192.94,-1317.35 382.56,-1317.35 ; 1271.56,-1317.35 1271.56,-707.36 ; 2538.56,-910.69 2538.56,-707.36 ; 3378.56,-910.69 3378.56,-707.36 ; 4000.56,-1323.85 4000.56,-1121.02
  text "ALL ARTWORK VIEWED FROM TOP SIDE" at -1129.94,-839.52 h60
  text "BOARD #:" at 1346.56,-839.52 h60
  text ".PRJ_Number" at 1892.06,-839.52 h60
  text "REV:" at 2736.56,-839.52 h60
  text ".PCB_Rev" at 3028.06,-839.52 h60
  text "SVN REV:" at 3574.56,-839.52 h60
  text ".VersionControl_RevNumber" at 4080.56,-839.52 h60
  text "LAYER NAME =" at -1129.94,-1042.35 h60
  text "TID #:" at 1346.56,-1042.86 h60
  text ".TID" at 1892.06,-1042.86 h60
  text "PLOT NAME =" at -1129.94,-1248.19 h60
  text ".plot_File_Name" at -324.44,-1248.19 h60
  text "GENERATED    :" at 1348.56,-1248.19 h60
  text ".Print_Date" at 2218.06,-1248.19 h60
  text ".Print_Time" at 2947.06,-1248.19 h60
  text "TEXAS INSTRUMENTS" at 4211.56,-1248.19 h60
M12 Stackup:
  drawing of 191 lines, arcs and shapes, not listed
  text "Layer" at 8896.41,7646.15 h60
  text "Name" at 9306.32,7646.15 h60
  text "Material" at 10236.06,7646.15 h60
  text "Thickness" at 11095.83,7646.15 h60
  text "Constant" at 11745.67,7646.15 h60
  text "Board Layer Stack" at 12315.53,7646.15 h60
  text "1" at 8896.41,7526.15 h60
  text "Top Overlay" at 9306.32,7526.15 h60
  text "2" at 8896.41,7406.15 h60
  text "Top Solder" at 9306.32,7406.15 h60
  text "Solder Resist" at 10236.06,7406.15 h60
  text "0.40mil" at 11095.83,7406.15 h60
  text "3.5" at 11745.67,7406.15 h60
  text "3" at 8896.41,7286.15 h60
  text "Top Layer" at 9306.32,7286.15 h60
  text "Copper" at 10236.06,7286.15 h60
  text "1.40mil" at 11095.83,7286.15 h60
  text "4" at 8896.41,7166.15 h60
  text "Dielectric1" at 9306.32,7166.15 h60
  text "FR-4 Hign Tg" at 10236.06,7166.15 h60
  text "59.20mil" at 11095.83,7166.15 h60
  text "4.8" at 11745.67,7166.15 h60
  text "5" at 8896.41,7046.15 h60
  text "Bottom Layer" at 9306.32,7046.15 h60
  text "Copper" at 10236.06,7046.15 h60
  text "1.40mil" at 11095.83,7046.15 h60
  text "6" at 8896.41,6926.15 h60
  text "Bottom Solder" at 9306.32,6926.15 h60
  text "Solder Resist" at 10236.06,6926.15 h60
  text "0.40mil" at 11095.83,6926.15 h60
  text "3.5" at 11745.67,6926.15 h60
  text "7" at 8896.41,6806.15 h60
  text "Bottom Overlay" at 9306.32,6806.15 h60
M13 Component Bodies Top:
  text ".Layer_Name" at -324.44,-1042.35 h60
M14 Component Bodies Bottom:
  text ".Layer_Name" at -324.44,-1042.35 h60
M15 Courtyards Top:
  text ".Layer_Name" at -324.44,-1042.35 h60
M16 Courtyards Bottom:
  text ".Layer_Name" at -324.44,-1042.35 h60
Drill Drawing:
  drawing of 181 lines, arcs and shapes, not listed
  text "Symbol" at 5965.71,6503.56 h72
  text "Quantity" at 6251.46,6503.56 h72
  text "Finished Hole Size" at 6568.64,6503.56 h72
  text "Plated" at 7190.38,6503.56 h72
  text "Hole Type" at 7434.71,6503.56 h72
  text "Hole Length" at 7795.05,6503.56 h72
  text "56" at 6251.46,6403.93 h60
  text "16.00mil (0.406mm)" at 6568.64,6403.93 h60
  text "PTH" at 7190.38,6403.93 h60
  text "Round" at 7434.71,6403.93 h60
  text "-" at 7795.05,6403.93 h60
  text "F" at 5944.08,6393.94 h44.28
  text "2" at 6251.46,6304.31 h60
  text "31.00mil (0.787mm)" at 6568.64,6304.31 h60
  text "PTH" at 7190.38,6304.31 h60
  text "Round" at 7434.71,6304.31 h60
  text "-" at 7795.05,6304.31 h60
  text "4" at 6251.46,6204.69 h60
  text "31.50mil (0.800mm)" at 6568.64,6204.69 h60
  text "PTH" at 7190.38,6204.69 h60
  text "Slot" at 7434.71,6204.69 h60
  text "76.77mil (1.950mm)" at 7795.05,6204.69 h60
  text "G" at 5944.08,6194.7 h44.28
  text "12" at 6251.46,6105.07 h60
  text "33.47mil (0.850mm)" at 6568.64,6105.07 h60
  text "PTH" at 7190.38,6105.07 h60
  text "Round" at 7434.71,6105.07 h60
  text "-" at 7795.05,6105.07 h60
  text "2" at 6251.46,6005.44 h60
  text "40.00mil (1.016mm)" at 6568.64,6005.44 h60
  text "NPTH" at 7190.38,6005.44 h60
  text "Slot" at 7434.71,6005.44 h60
  text "157.46mil (3.999mm)" at 7795.05,6005.44 h60
  text "H" at 5944.08,5995.45 h44.28
  text "2" at 6251.46,5905.82 h60
  text "40.00mil (1.016mm)" at 6568.64,5905.82 h60
  text "NPTH" at 7190.38,5905.82 h60
  text "Slot" at 7434.71,5905.82 h60
  text "157.48mil (4.000mm)" at 7795.05,5905.82 h60
  text "C" at 5944.08,5895.83 h44.28
  text "2" at 6251.46,5806.2 h60
  text "40.00mil (1.016mm)" at 6568.64,5806.2 h60
  text "NPTH" at 7190.38,5806.2 h60
  text "Slot" at 7434.71,5806.2 h60
  text "196.85mil (5.000mm)" at 7795.05,5806.2 h60
  text "2" at 6251.46,5706.58 h60
  text "40.00mil (1.016mm)" at 6568.64,5706.58 h60
  text "NPTH" at 7190.38,5706.58 h60
  text "Slot" at 7434.71,5706.58 h60
  text "236.22mil (6.000mm)" at 7795.05,5706.58 h60
  text "B" at 5944.08,5696.58 h44.28
  text "1" at 6251.46,5606.95 h60
  text "40.00mil (1.016mm)" at 6568.64,5606.95 h60
  text "NPTH" at 7190.38,5606.95 h60
  text "Slot" at 7434.71,5606.95 h60
  text "295.28mil (7.500mm)" at 7795.05,5606.95 h60
  text "D" at 5944.08,5596.96 h44.28
  text "1" at 6251.46,5507.33 h60
  text "40.00mil (1.016mm)" at 6568.64,5507.33 h60
  text "NPTH" at 7190.38,5507.33 h60
  text "Slot" at 7434.71,5507.33 h60
  text "393.70mil (10.000mm)" at 7795.05,5507.33 h60
  text "A" at 5944.08,5497.34 h44.28
  text "1" at 6251.46,5407.71 h60
  text "40.00mil (1.016mm)" at 6568.64,5407.71 h60
  text "NPTH" at 7190.38,5407.71 h60
  text "Slot" at 7434.71,5407.71 h60
  text "472.44mil (12.000mm)" at 7795.05,5407.71 h60
  text "1" at 6251.46,5308.09 h60
  text "40.00mil (1.016mm)" at 6568.64,5308.09 h60
  text "NPTH" at 7190.38,5308.09 h60
  text "Slot" at 7434.71,5308.09 h60
  text "520.00mil (13.208mm)" at 7795.05,5308.09 h60
  text "J" at 5944.08,5298.09 h44.28
  text "6" at 6251.46,5208.46 h60
  text "41.34mil (1.050mm)" at 6568.64,5208.46 h60
  text "PTH" at 7190.38,5208.46 h60
  text "Round" at 7434.71,5208.46 h60
  text "-" at 7795.05,5208.46 h60
  text "2" at 6251.46,5108.84 h60
  text "43.31mil (1.100mm)" at 6568.64,5108.84 h60
  text "NPTH" at 7190.38,5108.84 h60
  text "Round" at 7434.71,5108.84 h60
  text "-" at 7795.05,5108.84 h60
  text "2" at 6251.46,5009.22 h60
  text "43.31mil (1.100mm)" at 6568.64,5009.22 h60
  text "PTH" at 7190.38,5009.22 h60
  text "Round" at 7434.71,5009.22 h60
  text "-" at 7795.05,5009.22 h60
  text "4" at 6251.46,4909.6 h60
  text "45.28mil (1.150mm)" at 6568.64,4909.6 h60
  text "PTH" at 7190.38,4909.6 h60
  text "Round" at 7434.71,4909.6 h60
  text "-" at 7795.05,4909.6 h60
  text "6" at 6251.46,4809.97 h60
  text "50.00mil (1.270mm)" at 6568.64,4809.97 h60
  text "PTH" at 7190.38,4809.97 h60
  text "Round" at 7434.71,4809.97 h60
  text "-" at 7795.05,4809.97 h60
  text "8" at 6251.46,4710.35 h60
  text "51.18mil (1.300mm)" at 6568.64,4710.35 h60
  text "PTH" at 7190.38,4710.35 h60
  text "Round" at 7434.71,4710.35 h60
  text "-" at 7795.05,4710.35 h60
  text "2" at 6251.46,4610.73 h60
  text "51.18mil (1.300mm)" at 6568.64,4610.73 h60
  text "PTH" at 7190.38,4610.73 h60
  text "Round" at 7434.71,4610.73 h60
  text "-" at 7795.05,4610.73 h60
  text "I" at 5951.46,4600.74 h44.28
  text "4" at 6251.46,4511.11 h60
  text "53.15mil (1.350mm)" at 6568.64,4511.11 h60
  text "PTH" at 7190.38,4511.11 h60
  text "Round" at 7434.71,4511.11 h60
  text "-" at 7795.05,4511.11 h60
  text "1" at 6251.46,4411.48 h60
  text "60.00mil (1.524mm)" at 6568.64,4411.48 h60
  text "PTH" at 7190.38,4411.48 h60
  text "Round" at 7434.71,4411.48 h60
  text "-" at 7795.05,4411.48 h60
  text "14" at 6251.46,4311.86 h60
  text "62.99mil (1.600mm)" at 6568.64,4311.86 h60
  text "PTH" at 7190.38,4311.86 h60
  text "Round" at 7434.71,4311.86 h60
  text "-" at 7795.05,4311.86 h60
  text "3" at 6251.46,4212.24 h60
  text "64.96mil (1.650mm)" at 6568.64,4212.24 h60
  text "PTH" at 7190.38,4212.24 h60
  text "Round" at 7434.71,4212.24 h60
  text "-" at 7795.05,4212.24 h60
  text "L" at 5944.08,4202.25 h44.28
  text "3" at 6251.46,4112.62 h60
  text "125.98mil (3.200mm)" at 6568.64,4112.62 h60
  text "NPTH" at 7190.38,4112.62 h60
  text "Round" at 7434.71,4112.62 h60
  text "-" at 7795.05,4112.62 h60
  text "K" at 5944.08,4102.62 h44.28
  text "1" at 6251.46,4013 h60
  text "125.98mil (3.200mm)" at 6568.64,4013 h60
  text "PTH" at 7190.38,4013 h60
  text "Round" at 7434.71,4013 h60
  text "-" at 7795.05,4013 h60
  text "142 Total" at 6251.46,3913.37 h60
  text "Slot definitions :" at 5965.71,3833.76 h60
  text "Routed Path Length" at 6409.02,3833.76 h60
  text "= Calculated from tool start centre position to tool end centre position." at 6941.35,3833.76 h60
  text "Hole Length" at 6409.02,3784.03 h60
  text "= Routed Path Length + Tool Size = Slot length as defined in the PCB layout" at 6741.55,3784.03 h60
  text "Drill tolerances:" at 7541.7,2620 h60
  text "For 16 mil drill via +0/-16 mil" at 7525.7,2522 h60
  text "For PTH +/- 3 mil" at 7525.7,2378 h60
  text "For NPTH +/- 2 mil" at 7525.7,2237 h60
  text "NOTE:" at 7521.7,1632 h60
  text "1. 16 mil vias are tented" at 7523.7,1459 h60
  text "2. This not an impedance controlled board" at 7523.7,1306.37 h60
  text ".Layer_Name" at -324.44,-1042.35 h60
M17 Embedded Cavity:
  text ".Layer_Name" at -324.44,-1042.35 h60
M18 Embedded Assembly:
  text ".Layer_Name" at -324.44,-1042.35 h60
M19 Embedded Keepout:
  text ".Layer_Name" at -324.44,-1042.35 h60

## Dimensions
0,0 to 6157.71,-2 on M2 Board Dimensions
-961.49,-583.85 to 38.51,-583.85 on M2 Board Dimensions
6158.37,0 to 6157.71,2557.06 on M2 Board Dimensions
